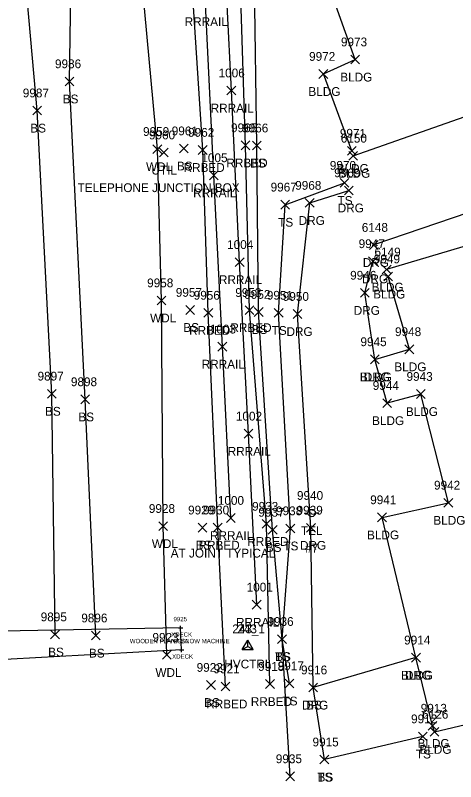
# Model space of a CAD drawing. Extents: x 1769141 to 1770817, y 735471 to 742405.
# Drawn here: x 1770148.8 to 1770248.9, y 740330.5 to 740504.9 of the extents above; entities that cross this region are included whole.
import ezdxf

# ---------------------------------------------------------------- set-up
doc = ezdxf.new("R2010")
doc.units = 0
for name, color, linetype in [('B_A', 7, 'Continuous'), ('B_C', 7, 'Continuous'), ('B_I', 7, 'Continuous'), ('B_TIC', 7, 'Continuous'), ('BELB', 7, 'Continuous'), ('C_A', 7, 'Continuous'), ('C_I', 7, 'Continuous'), ('CPSM', 7, 'Continuous'), ('L_A', 7, 'Continuous'), ('L_I', 7, 'Continuous'), ('L_TIC', 7, 'Continuous'), ('LAWA', 7, 'Continuous'), ('LBC', 7, 'Continuous'), ('LELB', 7, 'Continuous'), ('R_A', 7, 'Continuous'), ('R_C', 7, 'Continuous'), ('R_I', 7, 'Continuous'), ('R_TIC', 7, 'Continuous'), ('RDG', 7, 'Continuous'), ('RR', 7, 'Continuous'), ('RRB', 7, 'Continuous'), ('U_A', 7, 'Continuous'), ('U_C', 7, 'Continuous'), ('U_I', 7, 'Continuous'), ('UDEFAULT', 7, 'Continuous'), ('UP', 7, 'Continuous')]:
    doc.layers.add(name, color=color, linetype=linetype)

msp = doc.modelspace()

# ---------------------------------------------------------------- linework, layer by layer
at = {"layer": 'B_TIC'}
for p, q in [((1770186.36, 740365.48), (1770186.43, 740365.48)), ((1770186.58, 740360.47), (1770186.66, 740360.47)), ((1770186.58, 740360.47), (1770186.66, 740360.47))]:
    msp.add_line(p, q, dxfattribs=at)
for points in [[(1770185.86, 740365.48), (1770186.86, 740365.48)], [(1770186.36, 740364.98), (1770186.36, 740365.98)], [(1770186.08, 740360.47), (1770187.08, 740360.47)], [(1770186.08, 740360.47), (1770187.08, 740360.47)], [(1770186.58, 740359.97), (1770186.58, 740360.97)], [(1770186.58, 740359.97), (1770186.58, 740360.97)]]:
    msp.add_lwpolyline(points, dxfattribs=at)
at = {"layer": 'BELB'}
for points in [[(1770186.58, 740360.47), (1770186.36, 740365.48), (1770141.71, 740364.63), (1770142.22, 740358.03)], [(1770186.58, 740360.47), (1770142.22, 740358.03)]]:
    msp.add_lwpolyline(points, dxfattribs=at)
at = {"layer": 'CPSM'}
for p, q in [((1770200.36, 740360.53), (1770201.61, 740362.69)), ((1770200.36, 740360.53), (1770201.61, 740362.69)), ((1770202.86, 740360.53), (1770201.61, 740362.69)), ((1770201.61, 740361.25), (1770201.61, 740362.69)), ((1770202.86, 740360.53), (1770201.61, 740362.69)), ((1770201.61, 740361.25), (1770201.61, 740362.69)), ((1770200.36, 740360.53), (1770201.61, 740361.25)), ((1770200.36, 740360.53), (1770201.61, 740361.25)), ((1770200.36, 740360.53), (1770202.86, 740360.53)), ((1770200.36, 740360.53), (1770202.86, 740360.53)), ((1770201.61, 740361.25), (1770201.61, 740361.25)), ((1770201.61, 740361.25), (1770202.86, 740360.53)), ((1770201.61, 740361.25), (1770201.61, 740361.25)), ((1770201.61, 740361.25), (1770202.86, 740360.53))]:
    msp.add_line(p, q, dxfattribs=at)
at = {"layer": 'L_TIC'}
for points in [[(1770225.07, 740493.84), (1770227.07, 740495.84)], [(1770227.07, 740493.84), (1770225.07, 740495.84)], [(1770217.82, 740490.55), (1770219.82, 740492.55)], [(1770219.82, 740490.55), (1770217.82, 740492.55)], [(1770160.1, 740488.86), (1770162.1, 740490.86)], [(1770162.1, 740488.86), (1770160.1, 740490.86)], [(1770152.72, 740482.23), (1770154.72, 740484.23)], [(1770154.72, 740482.23), (1770152.72, 740484.23)], [(1770180.07, 740473.45), (1770182.07, 740475.45)], [(1770182.07, 740473.45), (1770180.07, 740475.45)], [(1770186.07, 740473.59), (1770188.07, 740475.59)], [(1770188.07, 740473.59), (1770186.07, 740475.59)], [(1770202.7, 740474.25), (1770204.7, 740476.25)], [(1770204.7, 740474.25), (1770202.7, 740476.25)], [(1770224.27, 740473.05), (1770226.27, 740475.05)], [(1770226.27, 740473.05), (1770224.27, 740475.05)], [(1770224.6, 740471.93), (1770226.6, 740473.93)], [(1770226.6, 740471.93), (1770224.6, 740473.93)], [(1770222.63, 740465.75), (1770224.63, 740467.75)], [(1770224.63, 740465.75), (1770222.63, 740467.75)], [(1770209.13, 740460.8), (1770211.13, 740462.8)], [(1770211.13, 740460.8), (1770209.13, 740462.8)], [(1770232.2, 740446.03), (1770234.2, 740448.03)], [(1770234.2, 740446.03), (1770232.2, 740448.03)], [(1770232.56, 740444.45), (1770234.56, 740446.45)], [(1770234.56, 740444.45), (1770232.56, 740446.45)], [(1770181, 740439), (1770183, 740441)], [(1770183, 740439), (1770181, 740441)], [(1770187.52, 740436.84), (1770189.52, 740438.84)], [(1770189.52, 740436.84), (1770187.52, 740438.84)], [(1770203.09, 740436.38), (1770205.09, 740438.38)], [(1770205.09, 740436.38), (1770203.09, 740438.38)], [(1770207.65, 740436.18), (1770209.65, 740438.18)], [(1770209.65, 740436.18), (1770207.65, 740438.18)], [(1770237.37, 740427.89), (1770239.37, 740429.89)], [(1770239.37, 740427.89), (1770237.37, 740429.89)], [(1770229.51, 740425.6), (1770231.51, 740427.6)], [(1770231.51, 740425.6), (1770229.51, 740427.6)], [(1770156.08, 740417.77), (1770158.08, 740419.77)], [(1770158.08, 740417.77), (1770156.08, 740419.77)], [(1770239.99, 740417.7), (1770241.99, 740419.7)], [(1770241.99, 740417.7), (1770239.99, 740419.7)], [(1770163.66, 740416.49), (1770165.66, 740418.49)], [(1770165.66, 740416.49), (1770163.66, 740418.49)], [(1770232.31, 740415.64), (1770234.31, 740417.64)], [(1770234.31, 740415.64), (1770232.31, 740417.64)], [(1770246.24, 740392.95), (1770248.24, 740394.95)], [(1770248.24, 740392.95), (1770246.24, 740394.95)], [(1770231.16, 740389.63), (1770233.16, 740391.63)], [(1770233.16, 740389.63), (1770231.16, 740391.63)], [(1770181.39, 740387.64), (1770183.39, 740389.64)], [(1770183.39, 740387.64), (1770181.39, 740389.64)], [(1770190.32, 740387.3), (1770192.32, 740389.3)], [(1770192.32, 740387.3), (1770190.32, 740389.3)], [(1770206.28, 740386.78), (1770208.28, 740388.78)], [(1770208.28, 740386.78), (1770206.28, 740388.78)], [(1770210.31, 740387.12), (1770212.31, 740389.12)], [(1770212.31, 740387.12), (1770210.31, 740389.12)], [(1770156.79, 740362.98), (1770158.79, 740364.98)], [(1770158.79, 740362.98), (1770156.79, 740364.98)], [(1770166.07, 740362.73), (1770168.07, 740364.73)], [(1770168.07, 740362.73), (1770166.07, 740364.73)], [(1770208.42, 740361.93), (1770210.42, 740363.93)], [(1770210.42, 740361.93), (1770208.42, 740363.93)], [(1770208.42, 740361.93), (1770210.42, 740363.93)], [(1770210.42, 740361.93), (1770208.42, 740363.93)], [(1770182.2, 740358.32), (1770184.2, 740360.32)], [(1770184.2, 740358.32), (1770182.2, 740360.32)], [(1770238.88, 740357.7), (1770240.88, 740359.7)], [(1770240.88, 740357.7), (1770238.88, 740359.7)], [(1770192.26, 740351.48), (1770194.26, 740353.48)], [(1770194.26, 740351.48), (1770192.26, 740353.48)], [(1770210.12, 740351.83), (1770212.12, 740353.83)], [(1770212.12, 740351.83), (1770210.12, 740353.83)], [(1770215.48, 740350.9), (1770217.48, 740352.9)], [(1770217.48, 740350.9), (1770215.48, 740352.9)], [(1770242.65, 740342.18), (1770244.65, 740344.18)], [(1770244.65, 740342.18), (1770242.65, 740344.18)], [(1770243.08, 740340.81), (1770245.08, 740342.81)], [(1770245.08, 740340.81), (1770243.08, 740342.81)], [(1770240.45, 740339.76), (1770242.45, 740341.76)], [(1770242.45, 740339.76), (1770240.45, 740341.76)], [(1770218.05, 740334.5), (1770220.05, 740336.5)], [(1770220.05, 740334.5), (1770218.05, 740336.5)], [(1770218.05, 740334.5), (1770220.05, 740336.5)], [(1770220.05, 740334.5), (1770218.05, 740336.5)], [(1770210.26, 740330.68), (1770212.26, 740332.68)], [(1770212.26, 740330.68), (1770210.26, 740332.68)]]:
    msp.add_lwpolyline(points, dxfattribs=at)
at = {"layer": 'LAWA'}
msp.add_lwpolyline([(1770183.2, 740359.32), (1770182.39, 740388.64), (1770182, 740440), (1770181.07, 740474.45), (1770177.73, 740510.73), (1770173.09, 740548.61), (1770171.04, 740591.04)], dxfattribs=at)
at = {"layer": 'LBC'}
for points in [[(1770225.6, 740472.93), (1770279.13, 740491.75), (1770265.37, 740529.79), (1770243.4, 740521.99), (1770224.13, 740515.23), (1770219.54, 740513.33)], [(1770225.27, 740474.05), (1770218.82, 740491.55), (1770226.07, 740494.84), (1770219.84, 740512.26)], [(1770244.08, 740341.81), (1770298.93, 740354.78), (1770287.18, 740403.8), (1770271.97, 740458.55), (1770233.2, 740447.03)], [(1770243.65, 740343.18), (1770239.88, 740358.7), (1770232.16, 740390.63), (1770247.24, 740393.95), (1770240.99, 740418.7), (1770233.31, 740416.64), (1770230.51, 740426.6), (1770238.37, 740428.89), (1770233.56, 740445.45)], [(1770244.08, 740341.81), (1770243.65, 740343.18)]]:
    msp.add_lwpolyline(points, dxfattribs=at)
at = {"layer": 'LELB'}
for points in [[(1770167.07, 740363.73), (1770164.66, 740417.49), (1770161.1, 740489.86), (1770161.79, 740535.19), (1770159.99, 740566.3), (1770156.13, 740597.65), (1770156.76, 740657.51)], [(1770157.79, 740363.98), (1770157.08, 740418.77), (1770153.72, 740483.23), (1770148.88, 740537.71), (1770150.37, 740576.07), (1770149.56, 740610.02), (1770143.11, 740653.52)], [(1770211.26, 740331.68), (1770209.42, 740362.93), (1770207.28, 740387.78), (1770204.09, 740437.38), (1770203.7, 740475.25), (1770203.15, 740512.06)], [(1770211.12, 740352.83), (1770209.42, 740362.93), (1770211.31, 740388.12), (1770208.65, 740437.18), (1770210.13, 740461.8), (1770223.63, 740466.75)], [(1770219.05, 740335.5), (1770216.48, 740351.9)], [(1770241.45, 740340.76), (1770219.05, 740335.5)]]:
    msp.add_lwpolyline(points, dxfattribs=at)
at = {"layer": 'R_TIC'}
for points in [[(1770196.9, 740486.78), (1770198.9, 740488.78)], [(1770198.9, 740486.78), (1770196.9, 740488.78)], [(1770190.37, 740473.26), (1770192.37, 740475.26)], [(1770192.37, 740473.26), (1770190.37, 740475.26)], [(1770200.12, 740474.3), (1770202.12, 740476.3)], [(1770202.12, 740474.3), (1770200.12, 740476.3)], [(1770192.92, 740467.48), (1770194.92, 740469.48)], [(1770194.92, 740467.48), (1770192.92, 740469.48)], [(1770223.59, 740464.05), (1770225.59, 740466.05)], [(1770225.59, 740464.05), (1770223.59, 740466.05)], [(1770214.71, 740461.2), (1770216.71, 740463.2)], [(1770216.71, 740461.2), (1770214.71, 740463.2)], [(1770229.29, 740451.63), (1770231.29, 740453.63)], [(1770231.29, 740451.63), (1770229.29, 740453.63)], [(1770198.78, 740447.72), (1770200.78, 740449.72)], [(1770200.78, 740447.72), (1770198.78, 740449.72)], [(1770229.1, 740447.92), (1770231.1, 740449.92)], [(1770231.1, 740447.92), (1770229.1, 740449.92)], [(1770227.23, 740440.73), (1770229.23, 740442.73)], [(1770229.23, 740440.73), (1770227.23, 740442.73)], [(1770201.04, 740436.8), (1770203.04, 740438.8)], [(1770203.04, 740436.8), (1770201.04, 740438.8)], [(1770191.65, 740436.18), (1770193.65, 740438.18)], [(1770193.65, 740436.18), (1770191.65, 740438.18)], [(1770211.94, 740435.91), (1770213.94, 740437.91)], [(1770213.94, 740435.91), (1770211.94, 740437.91)], [(1770194.85, 740428.49), (1770196.85, 740430.49)], [(1770196.85, 740428.49), (1770194.85, 740430.49)], [(1770229.51, 740425.6), (1770231.51, 740427.6)], [(1770231.51, 740425.6), (1770229.51, 740427.6)], [(1770200.77, 740408.67), (1770202.77, 740410.67)], [(1770202.77, 740408.67), (1770200.77, 740410.67)], [(1770196.75, 740389.49), (1770198.75, 740391.49)], [(1770198.75, 740389.49), (1770196.75, 740391.49)], [(1770204.87, 740388.14), (1770206.87, 740390.14)], [(1770206.87, 740388.14), (1770204.87, 740390.14)], [(1770193.79, 740387.3), (1770195.79, 740389.3)], [(1770195.79, 740387.3), (1770193.79, 740389.3)], [(1770215, 740387.26), (1770217, 740389.26)], [(1770217, 740387.26), (1770215, 740389.26)], [(1770202.66, 740369.75), (1770204.66, 740371.75)], [(1770204.66, 740369.75), (1770202.66, 740371.75)], [(1770238.88, 740357.7), (1770240.88, 740359.7)], [(1770240.88, 740357.7), (1770238.88, 740359.7)], [(1770195.54, 740351.14), (1770197.54, 740353.14)], [(1770197.54, 740351.14), (1770195.54, 740353.14)], [(1770205.67, 740351.7), (1770207.67, 740353.7)], [(1770207.67, 740351.7), (1770205.67, 740353.7)], [(1770215.48, 740350.9), (1770217.48, 740352.9)], [(1770217.48, 740350.9), (1770215.48, 740352.9)]]:
    msp.add_lwpolyline(points, dxfattribs=at)
at = {"layer": 'RDG'}
for points in [[(1770273.51, 740467.36), (1770230.29, 740452.63)], [(1770239.88, 740358.7), (1770216.48, 740351.9), (1770216, 740388.26), (1770212.94, 740436.91), (1770215.71, 740462.2), (1770224.59, 740465.05)], [(1770230.51, 740426.6), (1770228.23, 740441.73), (1770230.1, 740448.92)]]:
    msp.add_lwpolyline(points, dxfattribs=at)
at = {"layer": 'RR'}
for points in [[(1770197.75, 740390.49), (1770195.85, 740429.49), (1770193.92, 740468.48), (1770191.99, 740507.45), (1770190.02, 740546.42), (1770188.18, 740585.45), (1770186.34, 740624.52), (1770184.35, 740663.53), (1770182.41, 740702.58), (1770181.02, 740730.45), (1770179.25, 740766.27), (1770177.16, 740810.3), (1770173.74, 740877.11), (1770171.32, 740927.71), (1770169.45, 740967.98), (1770167.61, 741006.36), (1770166.54, 741027.4), (1770165.65, 741046.21), (1770163.84, 741084.65), (1770161.66, 741123.76), (1770160.41, 741153.19), (1770158.42, 741192.16), (1770156.87, 741228.02)], [(1770203.66, 740370.75), (1770201.77, 740409.67), (1770199.78, 740448.72), (1770197.9, 740487.78), (1770195.96, 740526.73), (1770194.09, 740565.77), (1770192.14, 740604.84), (1770190.28, 740643.85), (1770188.29, 740682.87), (1770186.41, 740721.83), (1770184.15, 740770), (1770182.62, 740801.29), (1770179.63, 740862.12), (1770176.86, 740918.91), (1770174.1, 740971.71), (1770172.22, 741013.51), (1770171.36, 741030.47), (1770170.33, 741051.22), (1770168.96, 741081.09), (1770166.99, 741119.98), (1770165.66, 741147.29), (1770164.69, 741163.32), (1770164.28, 741173.16), (1770162.44, 741212.29)]]:
    msp.add_lwpolyline(points, dxfattribs=at)
at = {"layer": 'RRB'}
for points in [[(1770196.54, 740352.14), (1770194.79, 740388.3), (1770192.65, 740437.18), (1770191.37, 740474.26), (1770189.05, 740510.42)], [(1770206.67, 740352.7), (1770205.87, 740389.14), (1770202.04, 740437.8), (1770201.12, 740475.3), (1770199.96, 740511.38)]]:
    msp.add_lwpolyline(points, dxfattribs=at)
at = {"layer": 'UDEFAULT'}
for points in [[(1770181.54, 740472.67), (1770183.54, 740474.67)], [(1770183.54, 740472.67), (1770181.54, 740474.67)]]:
    msp.add_lwpolyline(points, dxfattribs=at)
at = {"layer": 'UP'}
for p, q in [((1770214.49, 740391.61), (1770215.32, 740391.61)), ((1770216.15, 740391.62), (1770216.15, 740391.62)), ((1770217.82, 740391.62), (1770216.99, 740391.62)), ((1770216.99, 740391.62), (1770216.99, 740391.62)), ((1770217.82, 740391.62), (1770217.82, 740391.62))]:
    msp.add_line(p, q, dxfattribs=at)
msp.add_circle((1770216.15, 740391.62), 0.833, dxfattribs=at)

# ---------------------------------------------------------------- texts
at = {"layer": 'B_A'}
for p in [(1770184.2, 740363.48), (1770184.42, 740358.47), (1770184.42, 740358.47)]:
    msp.add_text('XDECK', height=1, dxfattribs=at).set_placement(p)
at = {"layer": 'B_C'}
msp.add_text('WOODEN PLANK SNOW MACHINE', height=1, dxfattribs=at).set_placement((1770174.8, 740361.98))
at = {"layer": 'B_I'}
for s, p in [('9925', (1770184.73, 740366.98)), ('9924', (1770184.95, 740361.97)), ('9924', (1770184.95, 740361.97))]:
    msp.add_text(s, height=1, dxfattribs=at).set_placement(p)
at = {"layer": 'C_A'}
msp.add_text('HVCTRL', height=2, dxfattribs=at).set_placement((1770196.3, 740356.25))
msp.add_text('HVCTRL', height=2, dxfattribs=at).set_placement((1770196.3, 740356.25))
at = {"layer": 'C_I'}
for s, p in [('243_1', (1770198.1, 740364.25)), ('243', (1770199.24, 740364.25))]:
    msp.add_text(s, height=2, dxfattribs=at).set_placement(p)
at = {"layer": 'L_A'}
for s, p in [('BLDG', (1770222.66, 740489.84)), ('BLDG', (1770215.42, 740486.55)), ('BS', (1770159.54, 740484.86)), ('BS', (1770152.16, 740478.23)), ('BS', (1770185.51, 740469.59)), ('BS', (1770202.14, 740470.25)), ('WDL', (1770178.49, 740469.45)), ('BLDG', (1770221.86, 740469.05)), ('BLDG', (1770222.19, 740467.93)), ('TS', (1770222.04, 740461.75)), ('TS', (1770208.54, 740456.8)), ('BLDG', (1770229.79, 740442.03)), ('BLDG', (1770230.15, 740440.45)), ('WDL', (1770179.41, 740435)), ('BS', (1770186.97, 740432.84)), ('BS', (1770202.53, 740432.38)), ('TS', (1770207.06, 740432.18)), ('BLDG', (1770234.96, 740423.89)), ('BLDG', (1770227.1, 740421.6)), ('BS', (1770155.52, 740413.77)), ('BLDG', (1770237.58, 740413.7)), ('BS', (1770163.1, 740412.49)), ('BLDG', (1770229.9, 740411.64)), ('BLDG', (1770243.83, 740388.95)), ('BLDG', (1770228.75, 740385.63)), ('WDL', (1770179.8, 740383.64)), ('BS', (1770189.76, 740383.3)), ('BS', (1770205.72, 740382.78)), ('TS', (1770209.72, 740383.12)), ('BS', (1770156.23, 740358.98)), ('BS', (1770165.51, 740358.73)), ('TS', (1770207.83, 740357.93)), ('BS', (1770207.86, 740357.93)), ('WDL', (1770180.62, 740354.32)), ('BLDG', (1770236.47, 740353.7)), ('BS', (1770191.7, 740347.48)), ('TS', (1770209.53, 740347.83)), ('BS', (1770214.92, 740346.9)), ('BLDG', (1770240.24, 740338.18)), ('TS', (1770239.86, 740335.76)), ('BLDG', (1770240.67, 740336.81)), ('TS', (1770217.46, 740330.5)), ('BS', (1770217.49, 740330.5))]:
    msp.add_text(s, height=2, dxfattribs=at).set_placement(p)
at = {"layer": 'L_I'}
for s, p in [('9973', (1770222.81, 740497.84)), ('9972', (1770215.57, 740494.55)), ('9986', (1770157.78, 740492.86)), ('9987', (1770150.46, 740486.23)), ('9966', (1770200.34, 740478.25)), ('9959', (1770177.81, 740477.45)), ('9961', (1770184.33, 740477.59)), ('9971', (1770222.57, 740477.05)), ('6150', (1770222.77, 740475.93)), ('9970', (1770220.29, 740469.75)), ('9967', (1770206.82, 740464.8)), ('6149', (1770230.45, 740450.03)), ('9949', (1770230.29, 740448.45)), ('9958', (1770178.74, 740443)), ('9957', (1770185.26, 740440.84)), ('9952', (1770200.83, 740440.38)), ('9951', (1770205.96, 740440.18)), ('9948', (1770235.11, 740431.89)), ('9945', (1770227.25, 740429.6)), ('9897', (1770153.82, 740421.77)), ('9943', (1770237.73, 740421.7)), ('9898', (1770161.4, 740420.49)), ('9944', (1770230.05, 740419.64)), ('9942', (1770243.98, 740396.95)), ('9941', (1770229.47, 740393.63)), ('9928', (1770179.13, 740391.64)), ('9929', (1770188.05, 740391.3)), ('9938', (1770208.05, 740391.12)), ('9937', (1770204.02, 740390.78)), ('9895', (1770154.53, 740366.98)), ('9896', (1770163.76, 740366.73)), ('9936', (1770206.1, 740365.93)), ('9936', (1770206.1, 740365.93)), ('9923', (1770179.95, 740362.32)), ('9914', (1770237.19, 740361.7)), ('9922', (1770190, 740355.48)), ('9917', (1770208.43, 740355.83)), ('9916', (1770213.73, 740354.9)), ('9913', (1770240.96, 740346.18)), ('6126', (1770241.29, 740344.81)), ('9912', (1770238.76, 740343.76)), ('9915', (1770216.35, 740338.5)), ('9915', (1770216.35, 740338.5)), ('9935', (1770208, 740334.68))]:
    msp.add_text(s, height=2, dxfattribs=at).set_placement(p)
at = {"layer": 'R_A'}
for s, p in [('RRRAIL', (1770187.28, 740502.45)), ('RRRAIL', (1770193.19, 740482.78)), ('RRBED', (1770196.77, 740470.3)), ('RRBED', (1770187.02, 740469.26)), ('RRRAIL', (1770189.21, 740463.48)), ('DRG', (1770222.08, 740460.05)), ('DRG', (1770213.2, 740457.2)), ('DRG', (1770227.78, 740447.63)), ('RRRAIL', (1770195.07, 740443.72)), ('DRG', (1770227.59, 740443.92)), ('DRG', (1770225.72, 740436.73)), ('RRBED', (1770188.29, 740432.18)), ('RRBED', (1770197.68, 740432.8)), ('DRG', (1770210.43, 740431.91)), ('RRRAIL', (1770191.15, 740424.49)), ('DRG', (1770228, 740421.6)), ('RRRAIL', (1770197.06, 740404.67)), ('RRRAIL', (1770193.04, 740385.49)), ('RRBED', (1770201.51, 740384.14)), ('RRBED', (1770190.43, 740383.3)), ('DRG', (1770213.49, 740383.26)), ('RRRAIL', (1770198.95, 740365.75)), ('DRG', (1770237.37, 740353.7)), ('RRBED', (1770202.32, 740347.7)), ('RRBED', (1770192.18, 740347.14)), ('DRG', (1770213.97, 740346.9))]:
    msp.add_text(s, height=2, dxfattribs=at).set_placement(p)
at = {"layer": 'R_C'}
msp.add_text('AT JOINT TYPICAL', height=2, dxfattribs=at).set_placement((1770184.1, 740381.49))
at = {"layer": 'R_I'}
for s, p in [('1006', (1770194.99, 740490.78)), ('9965', (1770197.81, 740478.3)), ('9962', (1770188.06, 740477.26)), ('1005', (1770191.07, 740471.48)), ('9969', (1770221.28, 740468.05)), ('9968', (1770212.41, 740465.2)), ('6148', (1770227.55, 740455.63)), ('1004', (1770196.93, 740451.72)), ('9947', (1770226.84, 740451.92)), ('9946', (1770224.91, 740444.73)), ('9956', (1770189.33, 740440.18)), ('9953', (1770198.78, 740440.8)), ('9950', (1770209.59, 740439.91)), ('1003', (1770193, 740432.49)), ('9945', (1770227.25, 740429.6)), ('1002', (1770198.92, 740412.67)), ('1000', (1770194.82, 740393.49)), ('9930', (1770191.44, 740391.3)), ('9933', (1770202.61, 740392.14)), ('9939', (1770212.73, 740391.26)), ('1001', (1770201.37, 740373.75)), ('9914', (1770237.19, 740361.7)), ('9921', (1770193.84, 740355.14)), ('9918', (1770203.98, 740355.7)), ('9916', (1770213.73, 740354.9))]:
    msp.add_text(s, height=2, dxfattribs=at).set_placement(p)
at = {"layer": 'U_A'}
for s, p in [('UTIL', (1770179.71, 740468.67)), ('TEL', (1770213.71, 740386.62))]:
    msp.add_text(s, height=2, dxfattribs=at).set_placement(p)
at = {"layer": 'U_C'}
for s, p in [('TELEPHONE JUNCTION BOX', (1770162.92, 740464.67)), ('#7', (1770214.69, 740382.62))]:
    msp.add_text(s, height=2, dxfattribs=at).set_placement(p)
at = {"layer": 'U_I'}
for s, p in [('9960', (1770179.15, 740476.67)), ('9940', (1770212.81, 740394.62))]:
    msp.add_text(s, height=2, dxfattribs=at).set_placement(p)

doc.saveas('drawing.dxf')
